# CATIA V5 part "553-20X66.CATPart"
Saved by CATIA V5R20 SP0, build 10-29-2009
Part number: 553-20X66
Definition: NONE
Nomenclature: 553-20X66
Source: Unknown
Description: 553-20X66
Bounding box of the stored display mesh (mm): x 0 to 66, y -15.5 to 15.5, z -15.5 to 15.5
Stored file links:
  C:\Users\Utente\Desktop\IO LAVORO\3D X SITO CF\X SITO\PLASTICA\553\553-20X66.CATPart
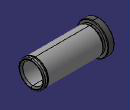
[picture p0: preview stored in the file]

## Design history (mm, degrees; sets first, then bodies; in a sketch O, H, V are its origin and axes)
Body1 "553-20X66" (main body)
  Solid1: solid without history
